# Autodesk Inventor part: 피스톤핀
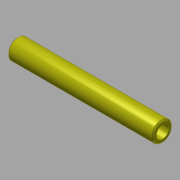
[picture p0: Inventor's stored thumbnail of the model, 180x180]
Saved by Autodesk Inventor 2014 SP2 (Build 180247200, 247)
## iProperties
Created: 2016-11
Part Number: 피스톤핀
Material: 강철, 탄소
Document SubType Name: Modeling
Designer: mduedu
Density: 7.87 g/cm^3
Mass: 13.9342 g
Surface Area: 24.1465 cm^2
Volume: 1.77055 cm^3
Appearance: 노란색
Author: mduedu
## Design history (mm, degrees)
sketch "스케치1"
  geometry: C1 r 2.5 at (0, 0); C2 r 4 at (0, 0); 1 further point
  constraints: 2 centre point, 2 coincident
  dimensions: "d0" = 5 diameter of C1; "d1" = 8 diameter of C2
extrude "돌출1" new body sketch "스케치1" stored distance "d2" = 58; taper "d3" = 0 deg
chamfer "모따기1" distance "d4" = 0.5; stored, may be unused: second distance "d5" = 2, angle "d6" = 45 deg
node "솔리드1"
